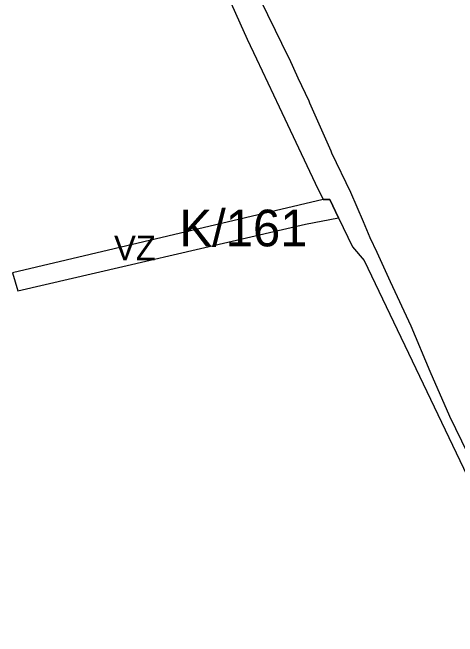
# Model space of a CAD drawing. Extents: x -521939 to -518034, y -1194984 to -1189555.
# Drawn here: x -520620.5 to -520438.4, y -1192213.7 to -1191958.5 of the extents above; entities that cross this region are included whole.
import ezdxf

# ---------------------------------------------------------------- set-up
doc = ezdxf.new("R2010")
doc.units = 0
for name, color, linetype in [('95420023', 7, 'Continuous'), ('96111023', 7, 'Continuous'), ('96202223', 7, 'Continuous')]:
    doc.layers.add(name, color=color, linetype=linetype)

msp = doc.modelspace()

# ---------------------------------------------------------------- linework, layer by layer
at = {"layer": '95420023'}
for points in [[(-520507.66, -1191976.43), (-520512.79, -1191965.9), (-520515.96, -1191959.4), (-520517.18, -1191956.82), (-520523.93, -1191944.46), (-520526.29, -1191938.72), (-520532.31, -1191922.75), (-520533.39, -1191919.77), (-520535.87, -1191912.92), (-520537.01, -1191909.76)], [(-520532.26, -1191951.92), (-520524.4, -1191969.39)], [(-520524.4, -1191969.39), (-520520.62, -1191977.39)], [(-520503.53, -1191985.28), (-520507.16, -1191977.44), (-520507.66, -1191976.43)], [(-520520.62, -1191977.39), (-520511.32, -1191997.09)], [(-520499.13, -1191994.79), (-520503.53, -1191985.28)], [(-520498.74, -1191995.62), (-520499.13, -1191994.79)], [(-520490.14, -1192015.17), (-520498.74, -1191995.62)], [(-520511.32, -1191997.09), (-520496.63, -1192028.24)], [(-520471.3, -1192056.68), (-520474.06, -1192050.59), (-520476.86, -1192044.07), (-520482.01, -1192032.05), (-520489.78, -1192015.99), (-520490.14, -1192015.17)], [(-520496.63, -1192028.24), (-520493.41, -1192035.03)], [(-520493.41, -1192035.03), (-520490.69, -1192035.01), (-520487.08, -1192042.46)], [(-520487.08, -1192042.46), (-520481.41, -1192054.32), (-520476.52, -1192059.92)], [(-520457.37, -1192086.83), (-520465.86, -1192068.71), (-520471.3, -1192056.68)], [(-520476.52, -1192059.92), (-520413.24, -1192192.22)], [(-520441.55, -1192123.72), (-520449.56, -1192105.3), (-520457.37, -1192086.83)], [(-520396.88, -1192213.72), (-520414.93, -1192177.76), (-520419.64, -1192168.56), (-520441.55, -1192123.72)]]:
    msp.add_lwpolyline(points, dxfattribs=at)
at = {"layer": '96111023'}
for points in [[(-520493.41, -1192035.03), (-520525.18, -1192042.5), (-520620.5, -1192064.91)], [(-520487.08, -1192042.46), (-520490.69, -1192035.01), (-520493.41, -1192035.03)], [(-520500.53, -1192045.04), (-520487.08, -1192042.46)], [(-520618.37, -1192072.35), (-520500.53, -1192045.04)], [(-520620.5, -1192064.91), (-520618.37, -1192072.35)]]:
    msp.add_lwpolyline(points, dxfattribs=at)
at = {"layer": '96202223'}
for points in [[(-520493.41, -1192035.03), (-520525.18, -1192042.5), (-520620.5, -1192064.91)], [(-520487.08, -1192042.46), (-520490.69, -1192035.01), (-520493.41, -1192035.03)], [(-520500.53, -1192045.04), (-520487.08, -1192042.46)], [(-520618.37, -1192072.35), (-520500.53, -1192045.04)], [(-520620.5, -1192064.91), (-520618.37, -1192072.35)]]:
    msp.add_lwpolyline(points, dxfattribs=at)

# ---------------------------------------------------------------- texts
at = {"layer": '96111023'}
msp.add_text('K/161', height=15, rotation=360, dxfattribs=at).set_placement((-520552.19, -1192054.13))
at = {"layer": '96202223'}
msp.add_text('VZ', height=10, rotation=360, dxfattribs=at).set_placement((-520578.92, -1192059.8))

doc.saveas('drawing.dxf')
